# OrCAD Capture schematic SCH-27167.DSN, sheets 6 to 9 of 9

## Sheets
6 Elevator Connectors: size C
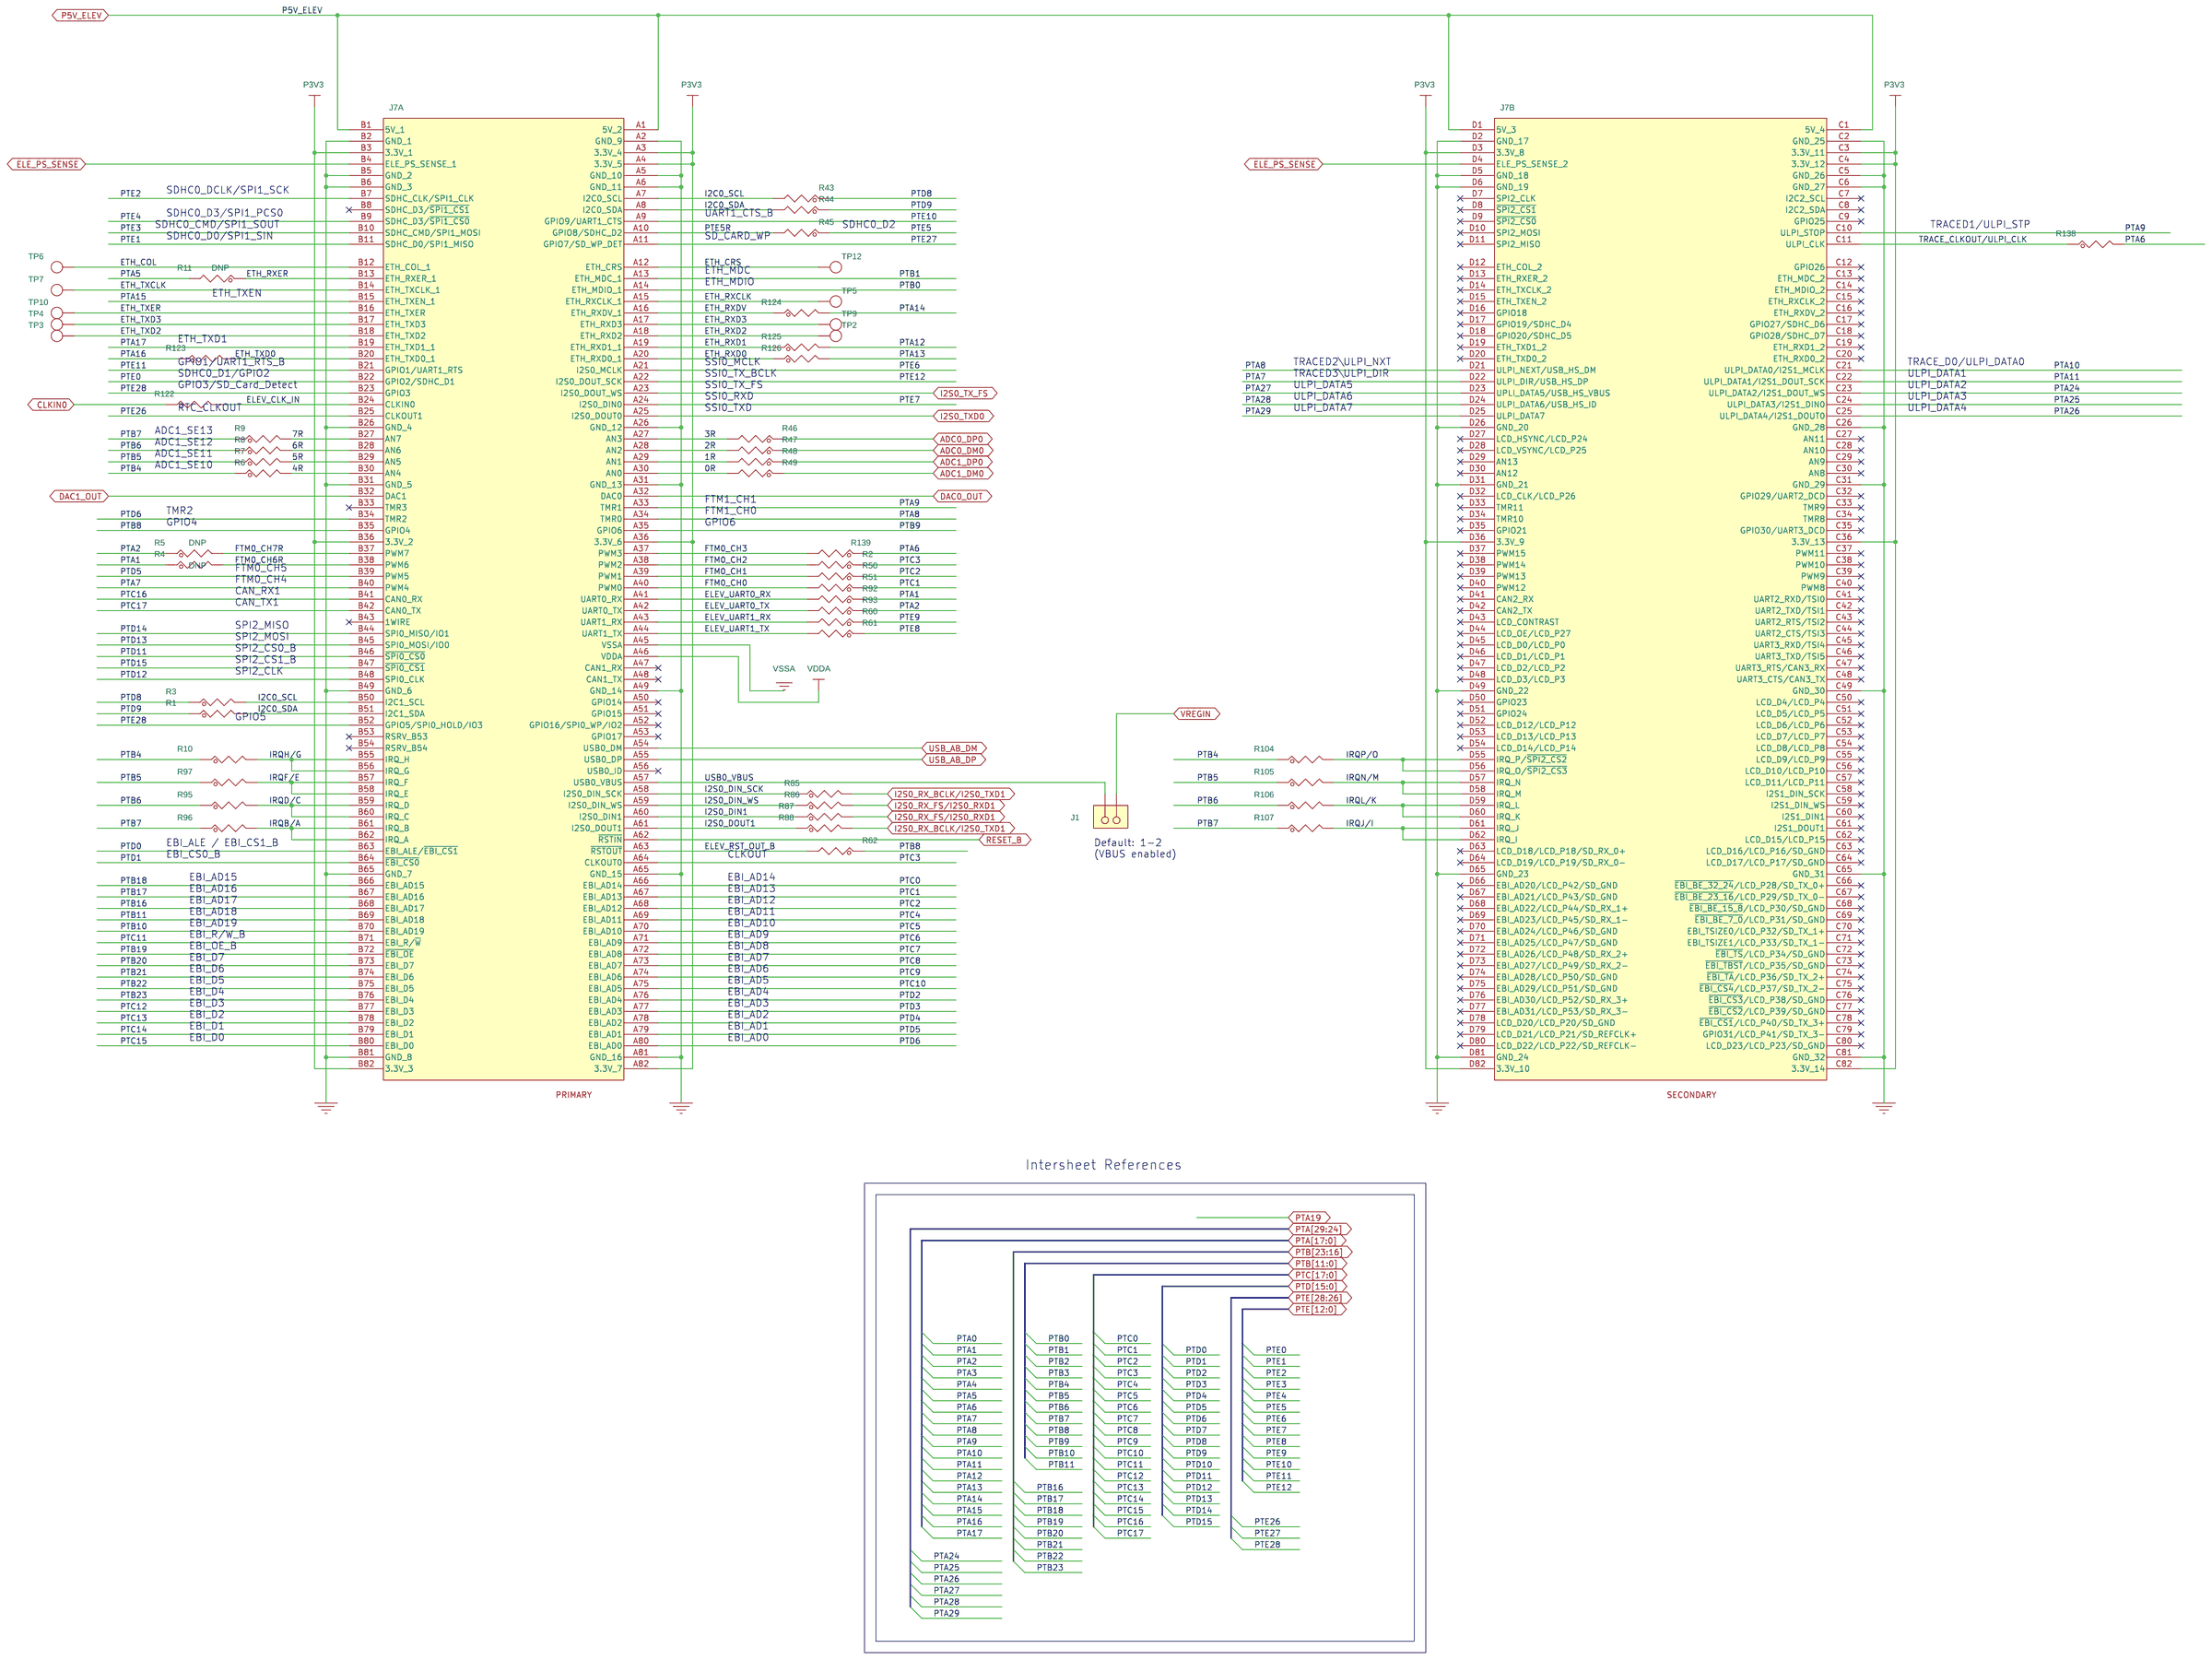
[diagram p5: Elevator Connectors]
7 02 Notes
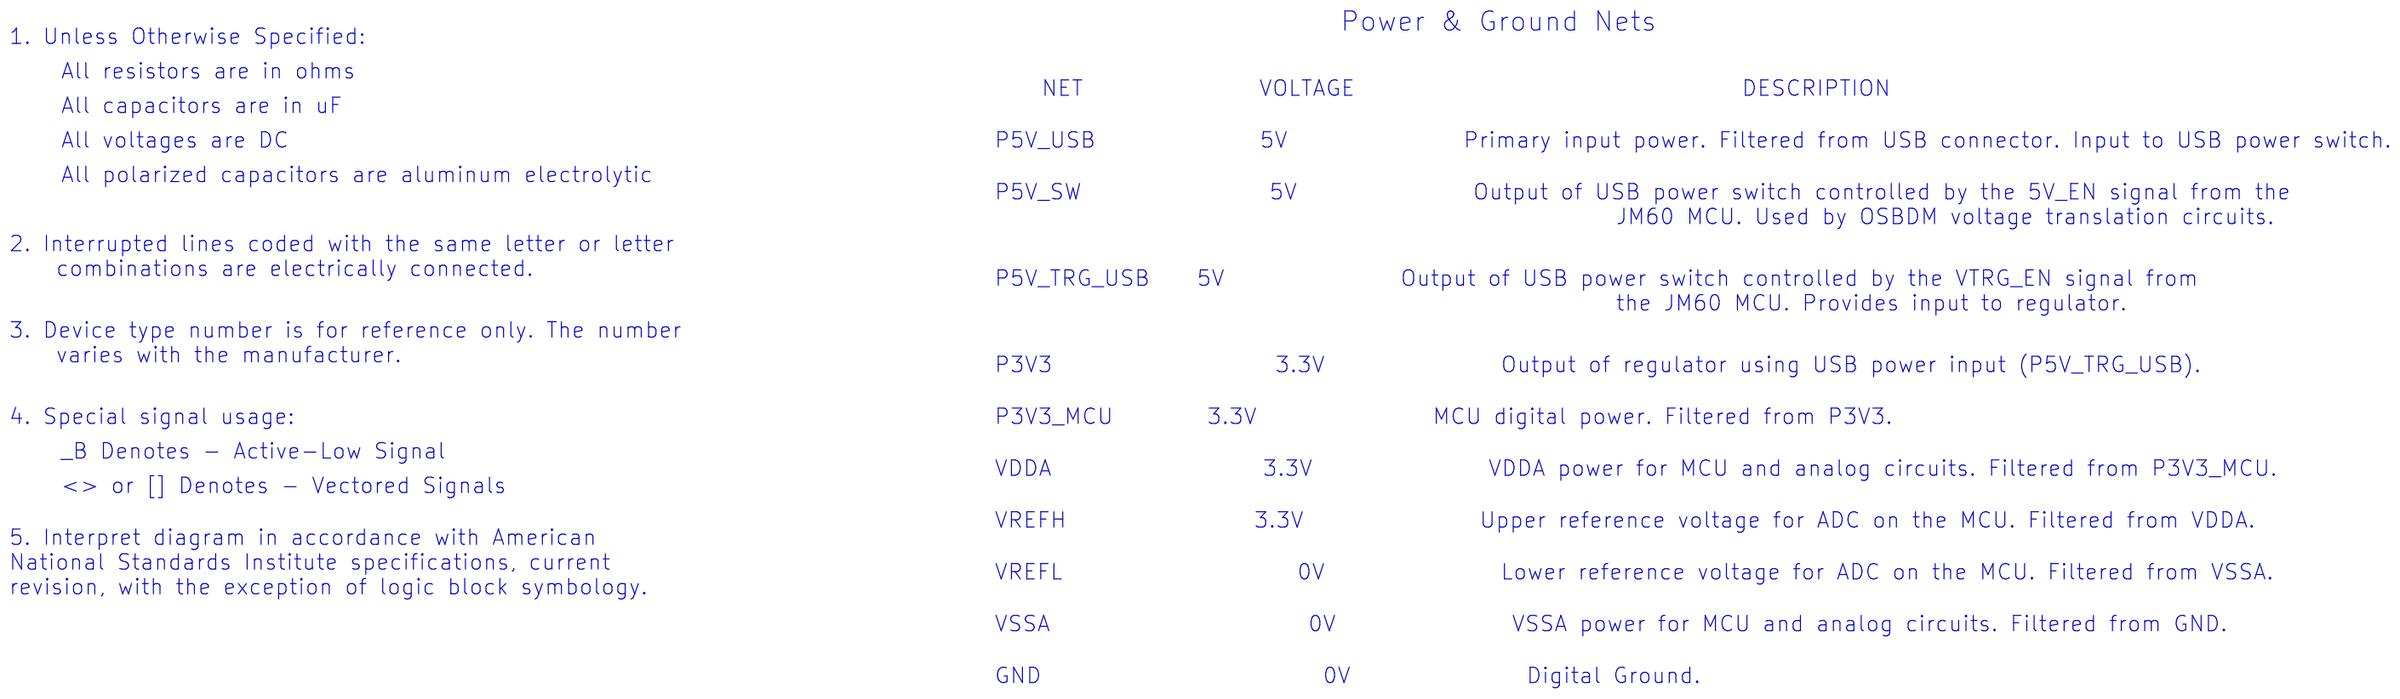
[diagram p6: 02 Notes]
8 03 Block Diagram
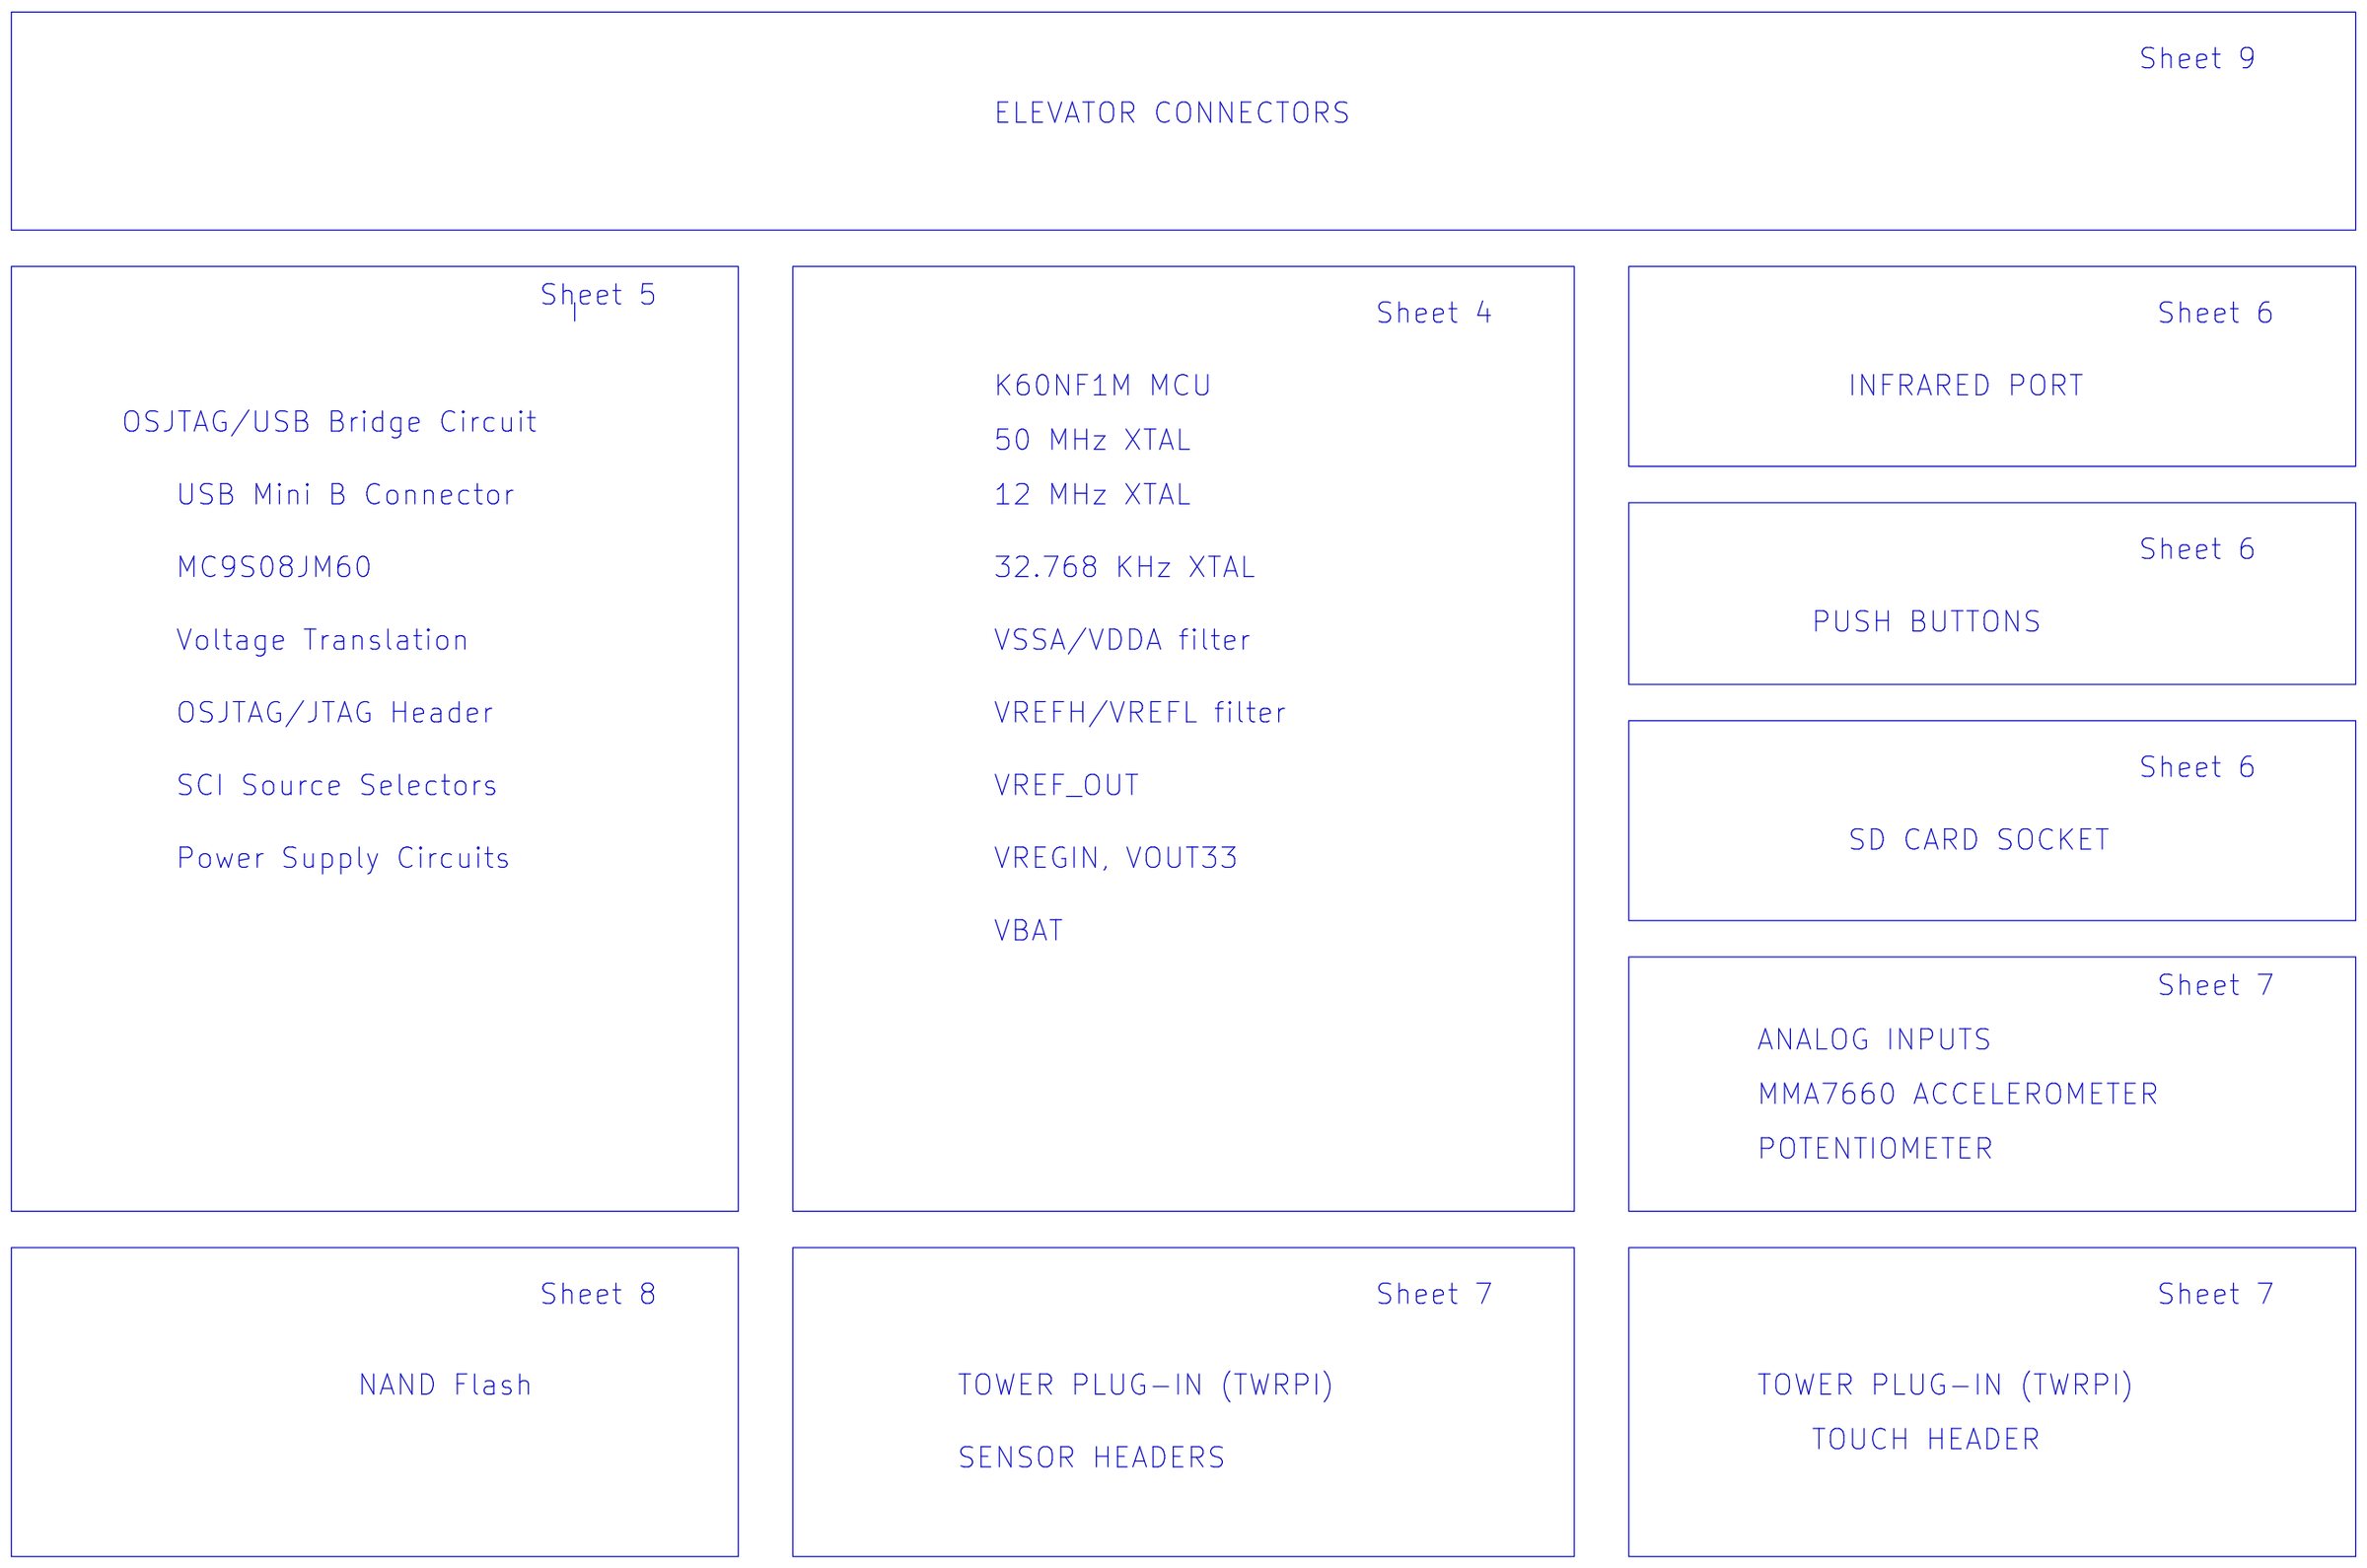
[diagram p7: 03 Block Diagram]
9 01 Table of Contents/Revisions
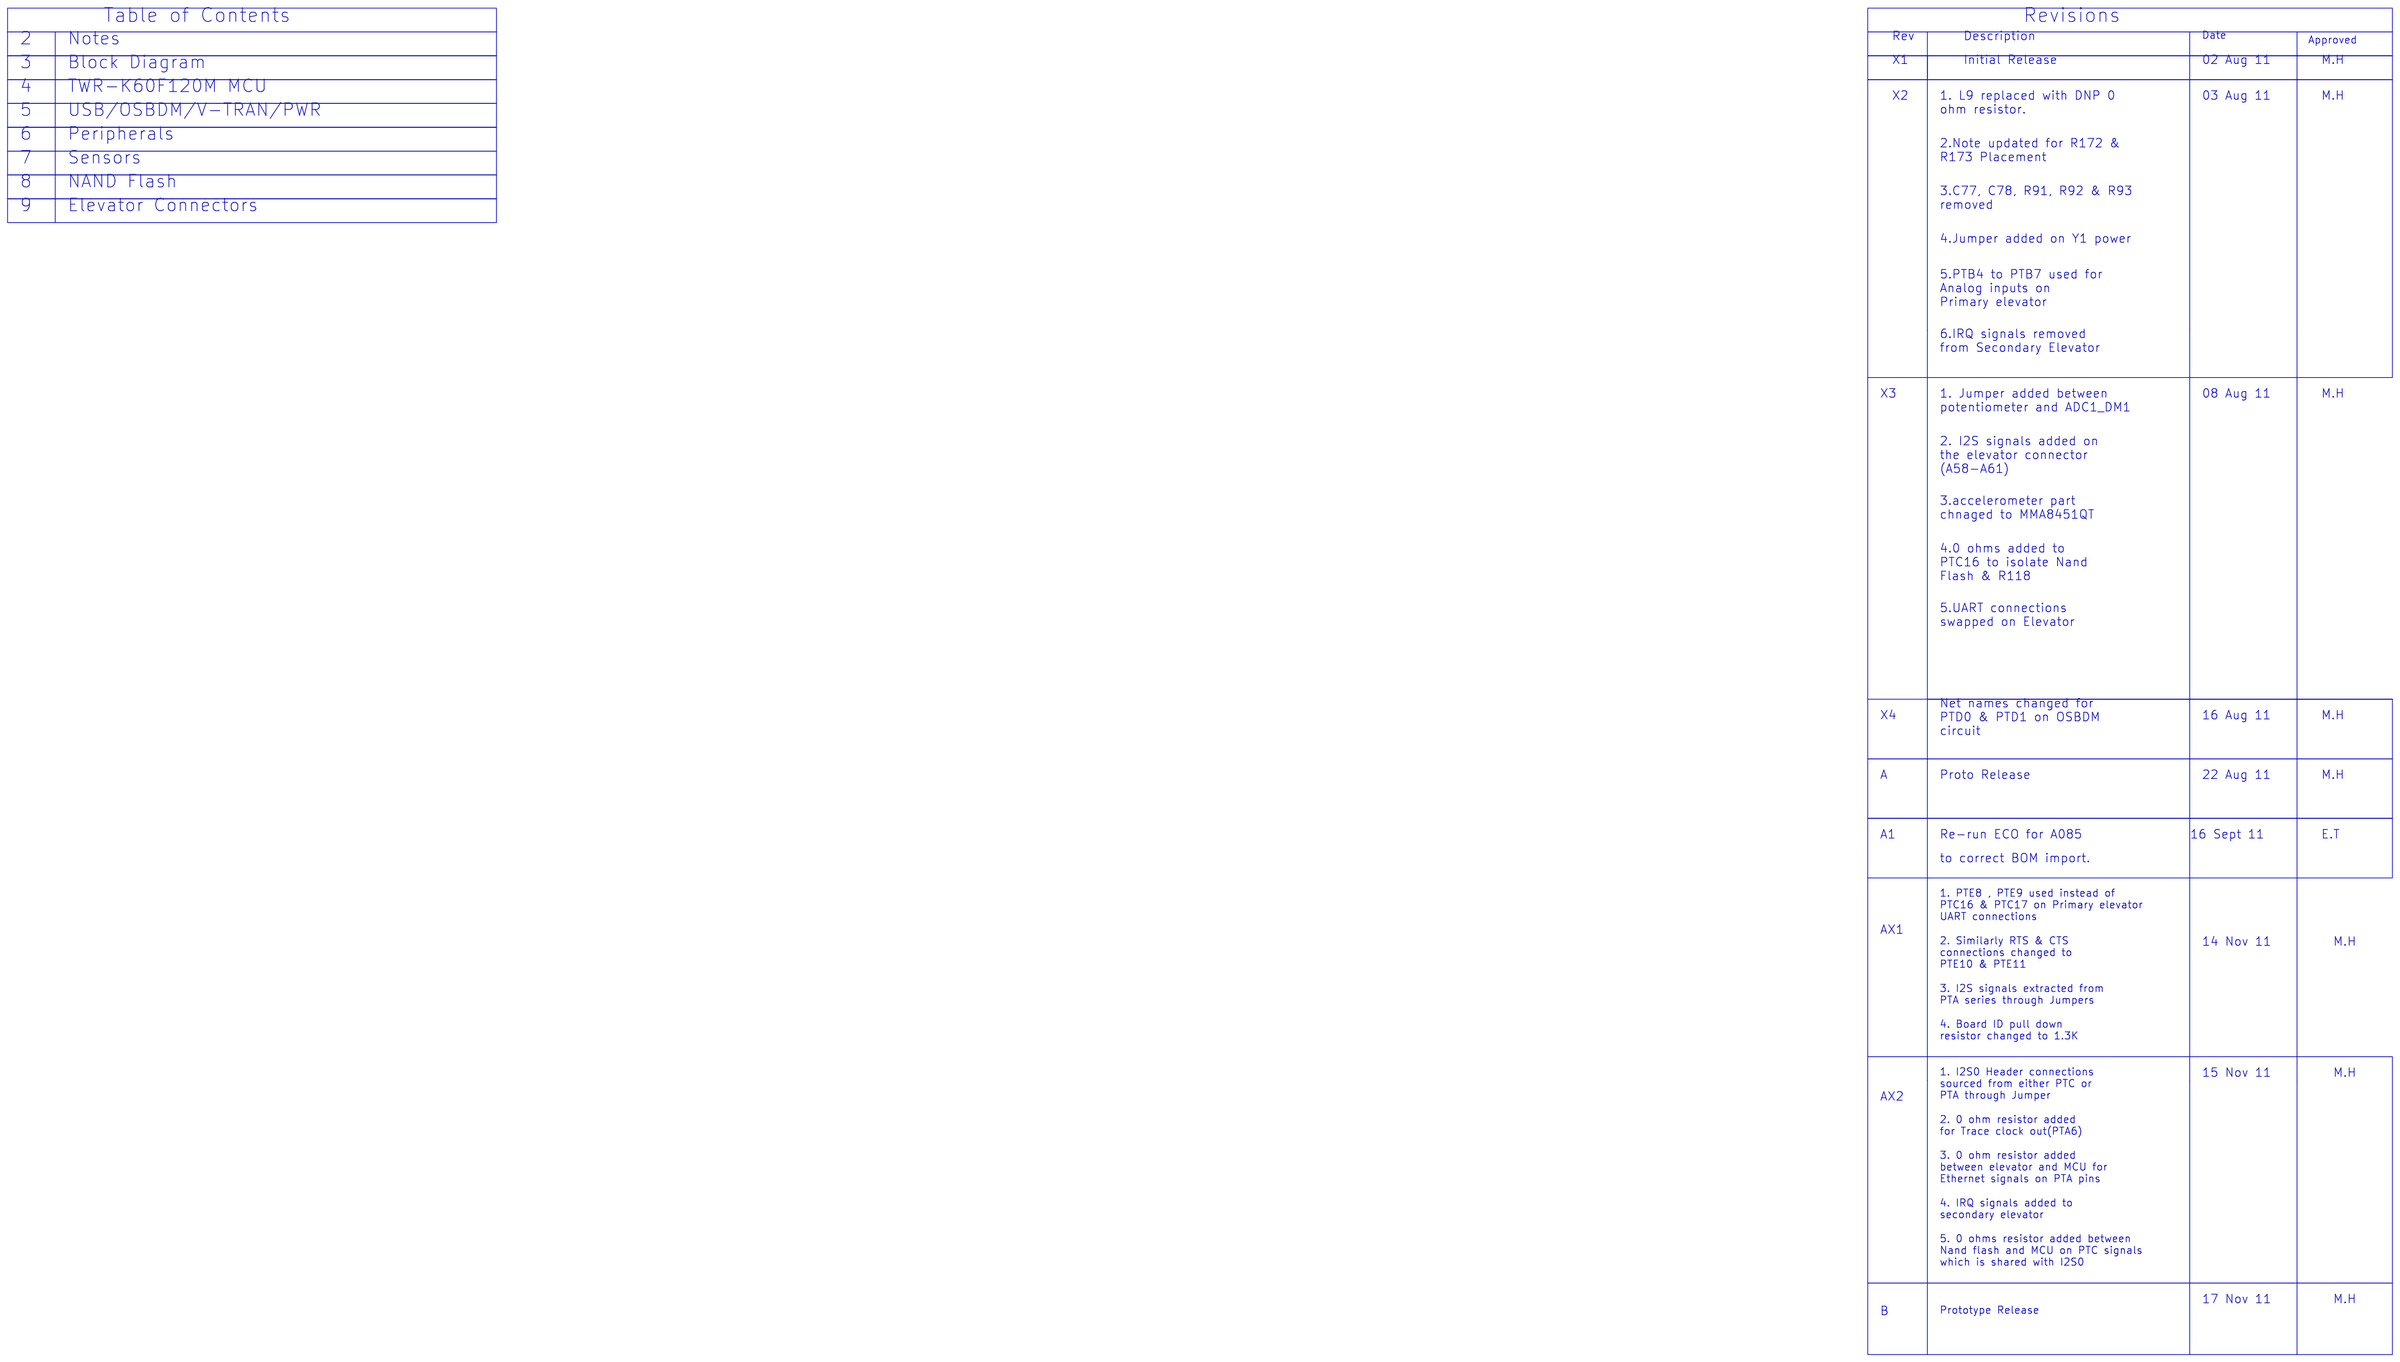
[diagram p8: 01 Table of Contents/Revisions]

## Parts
J1  HDR 1X2 TH  [HDR102]
J7  PCI EXPRESS TOWER SYSTEM  [cn2x82_finger_ass]  (sections A,B)
R1  0  [RC0603_OV]
R2  0  [RC0603_OV]
R3  0  [RC0603_OV]
R4  0  [RC0603_OV]
R5  0  [RC0603_OV]
R6  0  [RC0603_OV]
R7  0  [RC0603_OV]
R8  0  [RC0603_OV]
R9  0  [RC0603_OV]
R10  0  [RC0603_OV]
R11  0  [RC0603_OV]
R43  0  [RC0603_OV]
R44  0  [RC0603_OV]
R45  0  [RC0603_OV]
R46  0  [RC0603_OV]
R47  0  [RC0603_OV]
R48  0  [RC0603_OV]
R49  0  [RC0603_OV]
R50  0  [RC0603_OV]
R51  0  [RC0603_OV]
R60  0  [RC0603_OV]
R61  0  [RC0603_OV]
R62  0  [RC0603_OV]
R85  0  [RC0603_OV]
R86  0  [RC0603_OV]
R87  0  [RC0603_OV]
R88  0  [RC0603_OV]
R92  0  [RC0603_OV]
R93  0  [RC0603_OV]
R95  0  [RC0603_OV]
R96  0  [RC0603_OV]
R97  0  [RC0603_OV]
R104  0  [RC0603_OV]
R105  0  [RC0603_OV]
R106  0  [RC0603_OV]
R107  0  [RC0603_OV]
R122  0  [RC0603_OV]
R123  0  [RC0603_OV]
R124  0  [RC0603_OV]
R125  0  [RC0603_OV]
R126  0  [RC0603_OV]
R138  0  [RC0805_OV]
R139  0  [RC0805_OV]
TP2  TPAD_040  [TPAD_040]
TP3  TPAD_040  [TPAD_040]
TP4  TPAD_040  [TPAD_040]
TP5  TPAD_040  [TPAD_040]
TP6  TPAD_040  [TPAD_040]
TP7  TPAD_040  [TPAD_040]
TP9  TPAD_040  [TPAD_040]
TP10  TPAD_040  [TPAD_040]
TP12  TPAD_040  [TPAD_040]

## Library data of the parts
J1 = CONN_HDR_2X1: HDR 1X2 TH 100MIL SP 339H AU 98L; AGILE_PN: 210-75439; CAD_APPROVED: YES; HEIGHT: 8.71 MM; MFG_NAME01: SAMTEC; MFG_PN01: TSW-102-07-G-S; ROHS: Yes
J7 = CONN_PCI_XPRESS_X16_328P: CON DUAL 2X82 Edge PCI Express SMT 1MM SP 591H FOR TOWER SYSTEM NOT A PART TO ORDER; AGILE_PN: 211-78844; CAD_APPROVED: Yes; HEIGHT: 15.01MM; MFG_NAME01: NA; MFG_PN01: EDGE PCI EXPRESS 164; ROHS: Yes
R1-R3 R6-R10 R43-R51 R60-R62 R85-R88 R92 R93 R95-R97 R104-R107 R122-R126 = RES: RES MF ZERO OHM 1/10W -- 0603; AGILE_PN: 470-75407; CAD_APPROVED: Yes; FPLIST: RC0603_OV,RC0603,R603-X2,0603_CC; MFG_NAME01: VISHAY INTERTECHNOLOGY; MFG_PN01: CRCW06030000Z0EA; ROHS: Yes; Tolerance: 1%
R4 R5 R11 = RES: RES MF ZERO OHM 1/10W -- 0603; AGILE_PN: 470-75407; ASSY_OPT: DNP; CAD_APPROVED: Yes; FPLIST: RC0603_OV,RC0603,R603-X2,0603_CC; MFG_NAME01: VISHAY INTERTECHNOLOGY; MFG_PN01: CRCW06030000Z0EA; ROHS: Yes; Tolerance: 1%
R138 R139 = RES: RES MF ZERO OHM 1/8W -- 0805; AGILE_PN: 470-75442; CAD_APPROVED: Yes; FPLIST: RC0805_OV,RC0805,0805_CC; MFG_NAME01: YAGEO AMERICA; MFG_PN01: RC0805JR-070RL; ROHS: Yes; Tolerance: 5%
TP2-TP7 TP9 TP10 TP12 = TestLoop: TEST POINT PAD 40MIL DIA SMT, NO PART TO ORDER; AGILE_PN: 211-76643; CAD_APPROVED: Yes; HEIGHT: 0.1MM; MFG_NAME01: NOTACOMPONENT; MFG_PN01: NOTACOMPONENT; ROHS: Yes

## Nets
GND: J7.A2(GND_9) J7.A5(GND_10) J7.A6(GND_11) J7.A26(GND_12) J7.A31(GND_13) J7.A49(GND_14) J7.A65(GND_15) J7.A81(GND_16) J7.B2(GND_1) J7.B5(GND_2) J7.B6(GND_3) J7.B26(GND_4) J7.B31(GND_5) J7.B49(GND_6) J7.B65(GND_7) J7.B81(GND_8) J7.C2(GND_25) J7.C5(GND_26) J7.C6(GND_27) J7.C26(GND_28) J7.C31(GND_29) J7.C49(GND_30) J7.C65(GND_31) J7.C81(GND_32) J7.D2(GND_17) J7.D5(GND_18) J7.D6(GND_19) J7.D26(GND_20) J7.D31(GND_21) J7.D49(GND_22) J7.D65(GND_23) J7.D81(GND_24) ; also on sheet 1 2 3 4 5
P3V3: J7.A3(3.3V_4) J7.A4(3.3V_5) J7.A36(3.3V_6) J7.A82(3.3V_7) J7.B3(3.3V_1) J7.B36(3.3V_2) J7.B82(3.3V_3) J7.C3(3.3V_11) J7.C4(3.3V_12) J7.C36(3.3V_13) J7.C82(3.3V_14) J7.D3(3.3V_8) J7.D36(3.3V_9) J7.D82(3.3V_10) ; also on sheet 1 2 3 4 5
P5V_ELEV: J7.A1(5V_2) J7.B1(5V_1) J7.C1(5V_4) J7.D1(5V_3) ; also on sheet 2
VDDA: J7.A46(VDDA) ; also on sheet 1 4
VSSA: J7.A45(VSSA) ; also on sheet 1 4
0R: J7.A30(AN0) R49.2
1R: J7.A29(AN1) R48.2
2R: J7.A28(AN2) R47.2
3R: J7.A27(AN3) R46.2
4R: J7.B30(AN4) R6.2
5R: J7.B29(AN5) R7.2
6R: J7.B28(AN6) R8.2
7R: J7.B27(AN7) R9.2
ADC0_DM0: R47.1 ; also on sheet 1 4
ADC0_DP0: R46.1 ; also on sheet 1 4
ADC1_DM0: R49.1 ; also on sheet 1
ADC1_DP0: R48.1 ; also on sheet 1 4
CLKIN0: R122.1 ; also on sheet 1
DAC0_OUT: J7.A32(DAC0) ; also on sheet 1
DAC1_OUT: J7.B32(DAC1) ; also on sheet 1
ELE_PS_SENSE: J7.B4(ELE_PS_SENSE_1) J7.D4(ELE_PS_SENSE_2) ; also on sheet 2
ELEV_CLK_IN: J7.B24(CLKIN0) R122.2
ELEV_RST_OUT_B: J7.A63(~{RSTOUT}) R62.2
ELEV_UART0_RX: J7.A41(UART0_RX) R92.2
ELEV_UART0_TX: J7.A42(UART0_TX) R93.2
ELEV_UART1_RX: J7.A43(UART1_RX) R60.2
ELEV_UART1_TX: J7.A44(UART1_TX) R61.2
ETH_COL: J7.B12(ETH_COL_1) TP6.1(Pin1)
ETH_CRS: J7.A12(ETH_CRS) TP12.1(Pin1)
ETH_RXCLK: J7.A15(ETH_RXCLK_1) TP5.1(Pin1)
ETH_RXD0: J7.A20(ETH_RXD0_1) R126.1
ETH_RXD1: J7.A19(ETH_RXD1_1) R125.1
ETH_RXD2: J7.A18(ETH_RXD2) TP2.1(Pin1)
ETH_RXD3: J7.A17(ETH_RXD3) TP9.1(Pin1)
ETH_RXDV: J7.A16(ETH_RXDV_1) R124.1
ETH_RXER: J7.B13(ETH_RXER_1) R11.1
ETH_TXCLK: J7.B14(ETH_TXCLK_1) TP7.1(Pin1)
ETH_TXD0: J7.B20(ETH_TXD0_1) R123.2
ETH_TXD2: J7.B18(ETH_TXD2) TP3.1(Pin1)
ETH_TXD3: J7.B17(ETH_TXD3) TP4.1(Pin1)
ETH_TXER: J7.B16(ETH_TXER) TP10.1(Pin1)
FTM0_CH0: J7.A40(PWM0) R51.2
FTM0_CH1: J7.A39(PWM1) R50.2
FTM0_CH2: J7.A38(PWM2) R2.2
FTM0_CH3: J7.A37(PWM3) R139.2
FTM0_CH6R: J7.B38(PWM6) R4.2
FTM0_CH7R: J7.B37(PWM7) R5.2
I2C0_SCL: J7.A7(I2C0_SCL) J7.B50(I2C1_SCL) R3.2 R43.2
I2C0_SDA: J7.A8(I2C0_SDA) J7.B51(I2C1_SDA) R1.2 R44.2
I2S0_DIN1: J7.A60(I2S0_DIN1) R87.1
I2S0_DIN_SCK: J7.A58(I2S0_DIN_SCK) R85.1
I2S0_DIN_WS: J7.A59(I2S0_DIN_WS) R86.1
I2S0_DOUT1: J7.A61(I2S0_DOUT1) R88.1
I2S0_RX_BCLK/I2S0_TXD1: R85.2 R88.2 ; also on sheet 3
I2S0_RX_FS/I2S0_RXD1: R86.2 R87.2 ; also on sheet 3
I2S0_TX_FS: J7.A23(I2S0_DOUT_WS) ; also on sheet 3
I2S0_TXD0: J7.A25(I2S0_DOUT0) ; also on sheet 3
IRQB/A: J7.B61(IRQ_B) J7.B62(IRQ_A) R96.2
IRQD/C: J7.B59(IRQ_D) J7.B60(IRQ_C) R95.2
IRQF/E: J7.B57(IRQ_F) J7.B58(IRQ_E) R97.2
IRQH/G: J7.B55(IRQ_H) J7.B56(IRQ_G) R10.2
IRQJ/I: J7.D61(IRQ_J) J7.D62(IRQ_I) R107.2
IRQL/K: J7.D59(IRQ_L) J7.D60(IRQ_K) R106.2
IRQN/M: J7.D57(IRQ_N) J7.D58(IRQ_M) R105.2
IRQP/O: J7.D55(IRQ_P/~{SPI2_CS2}) J7.D56(IRQ_O/~{SPI2_CS3}) R104.2
PTA1: R4.1 R92.1 ; also on sheet 1 2
PTA2: R5.1 R93.1 ; also on sheet 1 2
PTA5: R11.2 ; also on sheet 1
PTA6: R138.2 R139.1 ; also on sheet 1 2
PTA7: J7.B40(PWM4) J7.D22(ULPI_DIR/USB_HS_DP) ; also on sheet 1 2
PTA8: J7.A34(TMR0) J7.D21(ULPI_NEXT/USB_HS_DM) ; also on sheet 1 2
PTA9: J7.A33(TMR1) J7.C10(ULPI_STOP) ; also on sheet 1 2
PTA10: J7.C21(ULPI_DATA0/I2S1_MCLK) ; also on sheet 1 2 4
PTA11: J7.C22(ULPI_DATA1/I2S1_DOUT_SCK) ; also on sheet 1 4
PTA12: R125.2 ; also on sheet 1 3
PTA13: R126.2 ; also on sheet 1 3
PTA14: R124.2 ; also on sheet 1 3
PTA15: J7.B15(ETH_TXEN_1) ; also on sheet 1
PTA16: R123.1 ; also on sheet 1 3
PTA17: J7.B19(ETH_TXD1_1) ; also on sheet 1
PTA24: J7.C23(ULPI_DATA2/I2S1_DOUT_WS) ; also on sheet 1
PTA25: J7.C24(ULPI_DATA3/I2S1_DIN0) ; also on sheet 1
PTA26: J7.C25(ULPI_DATA4/I2S1_DOUT0) ; also on sheet 1
PTA27: J7.D23(UPLI_DATA5/USB_HS_VBUS) ; also on sheet 1
PTA28: J7.D24(ULPI_DATA6/USB_HS_ID) ; also on sheet 1 4
PTA29: J7.D25(ULPI_DATA7) ; also on sheet 1 4
PTB0: J7.A14(ETH_MDIO_1) ; also on sheet 1 4
PTB1: J7.A13(ETH_MDC_1) ; also on sheet 1 4
PTB4: R6.1 R10.1 R104.1 ; also on sheet 1 4
PTB5: R7.1 R97.1 R105.1 ; also on sheet 1
PTB6: R8.1 R95.1 R106.1 ; also on sheet 1
PTB7: R9.1 R96.1 R107.1 ; also on sheet 1 4
PTB8: J7.B35(GPIO4) R62.1 ; also on sheet 1 4
PTB9: J7.A35(GPIO6) ; also on sheet 1 4
PTB10: J7.B70(EBI_AD19) ; also on sheet 1
PTB11: J7.B69(EBI_AD18) ; also on sheet 1
PTB16: J7.B68(EBI_AD17) ; also on sheet 1 4
PTB17: J7.B67(EBI_AD16) ; also on sheet 1 4
PTB18: J7.B66(EBI_AD15) ; also on sheet 1 4
PTB19: J7.B72(~{EBI_OE}) ; also on sheet 1 4
PTB20: J7.B73(EBI_D7) ; also on sheet 1 5
PTB21: J7.B74(EBI_D6) ; also on sheet 1 5
PTB22: J7.B75(EBI_D5) ; also on sheet 1 5
PTB23: J7.B76(EBI_D4) ; also on sheet 1 5
PTC0: J7.A66(EBI_AD14) ; also on sheet 1 3 4 5
PTC1: J7.A67(EBI_AD13) R51.1 ; also on sheet 1 3 4 5
PTC2: J7.A68(EBI_AD12) R50.1 ; also on sheet 1 3 4 5
PTC3: J7.A64(CLKOUT0) R2.1 ; also on sheet 1
PTC4: J7.A69(EBI_AD11) ; also on sheet 1 5
PTC5: J7.A70(EBI_AD10) ; also on sheet 1 5
PTC6: J7.A71(EBI_AD9) ; also on sheet 1 3 5
PTC7: J7.A72(EBI_AD8) ; also on sheet 1 5
PTC8: J7.A73(EBI_AD7) ; also on sheet 1 5
PTC9: J7.A74(EBI_AD6) ; also on sheet 1 5
PTC10: J7.A75(EBI_AD5) ; also on sheet 1 5
PTC11: J7.B71(EBI_R/~{W}) ; also on sheet 1 3 5
PTC12: J7.B77(EBI_D3) ; also on sheet 1
PTC13: J7.B78(EBI_D2) ; also on sheet 1
PTC14: J7.B79(EBI_D1) ; also on sheet 1
PTC15: J7.B80(EBI_D0) ; also on sheet 1
PTC16: J7.B41(CAN0_RX) ; also on sheet 1 5
PTC17: J7.B42(CAN0_TX) ; also on sheet 1 5
PTD0: J7.B63(EBI_ALE/~{EBI_CS1}) ; also on sheet 1
PTD1: J7.B64(~{EBI_CS0}) ; also on sheet 1
PTD2: J7.A76(EBI_AD4) ; also on sheet 1
PTD3: J7.A77(EBI_AD3) ; also on sheet 1
PTD4: J7.A78(EBI_AD2) ; also on sheet 1 5
PTD5: J7.A79(EBI_AD1) J7.B39(PWM5) ; also on sheet 1 5
PTD6: J7.A80(EBI_AD0) J7.B34(TMR2) ; also on sheet 1
PTD8: R3.1 R43.1 ; also on sheet 1 4 5
PTD9: R1.1 R44.1 ; also on sheet 1 4 5
PTD11: J7.B46(~{SPI0_CS0}) ; also on sheet 1
PTD12: J7.B48(SPI0_CLK) ; also on sheet 1 4
PTD13: J7.B45(SPI0_MOSI/IO0) ; also on sheet 1 4
PTD14: J7.B44(SPI0_MISO/IO1) ; also on sheet 1 4
PTD15: J7.B47(~{SPI0_CS1}) ; also on sheet 1 4
PTE0: J7.B22(GPIO2/SDHC_D1) ; also on sheet 1 3
PTE1: J7.B11(SDHC_D0/SPI1_MISO) ; also on sheet 1 3
PTE2: J7.B7(SDHC_CLK/SPI1_CLK) ; also on sheet 1 3
PTE3: J7.B10(SDHC_CMD/SPI1_MOSI) ; also on sheet 1 3
PTE4: J7.B9(SDHC_D3/~{SPI1_CS0}) ; also on sheet 1 3
PTE5: R45.1 ; also on sheet 1 3
PTE5R: J7.A10(GPIO8/SDHC_D2) R45.2
PTE6: J7.A21(I2S0_MCLK) ; also on sheet 1
PTE7: J7.A24(I2S0_DIN0) ; also on sheet 1
PTE8: R61.1 ; also on sheet 1 2
PTE9: R60.1 ; also on sheet 1 2
PTE10: J7.A9(GPIO9/UART1_CTS) ; also on sheet 1
PTE11: J7.B21(GPIO1/UART1_RTS) ; also on sheet 1
PTE12: J7.A22(I2S0_DOUT_SCK) ; also on sheet 1
PTE26: J7.B25(CLKOUT1) ; also on sheet 1 3 4
PTE27: J7.A11(GPIO7/SD_WP_DET) ; also on sheet 1
PTE28: J7.B23(GPIO3) J7.B52(GPIO5/SPI0_HOLD/IO3) ; also on sheet 1 3
RESET_B: J7.A62(~{RSTIN}) ; also on sheet 1 2 4
TRACE_CLKOUT/ULPI_CLK: J7.C11(ULPI_CLK) R138.1
USB0_VBUS: J1.2 J7.A57(USB0_VBUS)
USB_AB_DM: J7.A54(USB0_DM) ; also on sheet 1
USB_AB_DP: J7.A55(USB0_DP) ; also on sheet 1
VREGIN: J1.1 ; also on sheet 1

Not connected (* = marked no-connect by the designer): J7 A47(CAN1_RX)* A48(CAN1_TX)* A50(GPIO14)* A51(GPIO15)* A52(GPIO16/SPI0_WP/IO2)* A53(GPIO17)* A56(USB0_ID)* B8(SDHC_D3/~{SPI1_CS1})* B33(TMR3)* B43(1WIRE)* B53(RSRV)* B54(RSRV)* C7(I2C2_SCL)* C8(I2C2_SDA)* C9(GPIO25)* C12(GPIO26)* C13(ETH_MDC_2)* C14(ETH_MDIO_2)* C15(ETH_RXCLK_2)* C16(ETH_RXDV_2)* C17(GPIO27/SDHC_D6)* C18(GPIO28/SDHC_D7)* C19(ETH_RXD1_2)* C20(ETH_RXD0_2)* C27(AN11)* C28(AN10)* C29(AN9)* C30(AN8)* C32(GPIO29/UART2_DCD)* C33(TMR9)* C34(TMR8)* C35(GPIO30/UART3_DCD)* C37(PWM11)* C38(PWM10)* C39(PWM9)* C40(PWM8)* C41(UART2_RXD/TSI0)* C42(UART2_TXD/TSI1)* C43(UART2_RTS/TSI2)* C44(UART2_CTS/TSI3)* C45(UART3_RXD/TSI4)* C46(UART3_TXD/TSI5)* C47(UART3_RTS/CAN3_RX)* C48(UART3_CTS/CAN3_TX)* C50(LCD_D4/LCD_P4)* C51(LCD_D5/LCD_P5)* C52(LCD_D6/LCD_P6)* C53(LCD_D7/LCD_P7)* C54(LCD_D8/LCD_P8)* C55(LCD_D9/LCD_P9)* C56(LCD_D10/LCD_P10)* C57(LCD_D11/LCD_P11)* C58(I2S1_DIN_SCK)* C59(I2S1_DIN_WS)* C60(I2S1_DIN1)* C61(I2S1_DOUT1)* C62(LCD_D15/LCD_P15)* C63(LCD_D16/LCD_P16/SD_GND)* C64(LCD_D17/LCD_P17/SD_GND)* C66(~{EBI_BE_32_24}/LCD_P28/SD_TX_0+)* C67(~{EBI_BE_23_16}/LCD_P29/SD_TX_0-)* C68(~{EBI_BE_15_8}/LCD_P30/SD_GND)* C69(~{EBI_BE_7_0}/LCD_P31/SD_GND)* C70(EBI_TSIZE0/LCD_P32/SD_TX_1+)* C71(EBI_TSIZE1/LCD_P33/SD_TX_1-)* C72(~{EBI_TS}/LCD_P34/SD_GND)* C73(~{EBI_TBST}/LCD_P35/SD_GND)* C74(~{EBI_TA}/LCD_P36/SD_TX_2+)* C75(~{EBI_CS4}/LCD_P37/SD_TX_2-)* C76(~{EBI_CS3}/LCD_P38/SD_GND)* C77(~{EBI_CS2}/LCD_P39/SD_GND)* C78(~{EBI_CS1}/LCD_P40/SD_TX_3+)* C79(GPIO31/LCD_P41/SD_TX_3-)* C80(LCD_D23/LCD_P23/SD_GND)* D7(SPI2_CLK)* D8(~{SPI2_CS1})* D9(~{SPI2_CS0})* D10(SPI2_MOSI)* D11(SPI2_MISO)* D12(ETH_COL_2)* D13(ETH_RXER_2)* D14(ETH_TXCLK_2)* D15(ETH_TXEN_2)* D16(GPIO18)* D17(GPIO19/SDHC_D4)* D18(GPIO20/SDHC_D5)* D19(ETH_TXD1_2)* D20(ETH_TXD0_2)* D27(LCD_HSYNC/LCD_P24)* D28(LCD_VSYNC/LCD_P25)* D29(AN13)* D30(AN12)* D32(LCD_CLK/LCD_P26)* D33(TMR11)* D34(TMR10)* D35(GPIO21)* D37(PWM15)* D38(PWM14)* D39(PWM13)* D40(PWM12)* D41(CAN2_RX)* D42(CAN2_TX)* D43(LCD_CONTRAST)* D44(LCD_OE/LCD_P27)* D45(LCD_D0/LCD_P0)* D46(LCD_D1/LCD_P1)* D47(LCD_D2/LCD_P2)* D48(LCD_D3/LCD_P3)* D50(GPIO23)* D51(GPIO24)* D52(LCD_D12/LCD_P12)* D53(LCD_D13/LCD_P13)* D54(LCD_D14/LCD_P14)* D63(LCD_D18/LCD_P18/SD_RX_0+)* D64(LCD_D19/LCD_P19/SD_RX_0-)* D66(EBI_AD20/LCD_P42/SD_GND)* D67(EBI_AD21/LCD_P43/SD_GND)* D68(EBI_AD22/LCD_P44/SD_RX_1+)* D69(EBI_AD23/LCD_P45/SD_RX_1-)* D70(EBI_AD24/LCD_P46/SD_GND)* D71(EBI_AD25/LCD_P47/SD_GND)* D72(EBI_AD26/LCD_P48/SD_RX_2+)* D73(EBI_AD27/LCD_P49/SD_RX_2-)* D74(EBI_AD28/LCD_P50/SD_GND)* D75(EBI_AD29/LCD_P51/SD_GND)* D76(EBI_AD30/LCD_P52/SD_RX_3+)* D77(EBI_AD31/LCD_P53/SD_RX_3-)* D78(LCD_D20/LCD_P20/SD_GND)* D79(LCD_D21/LCD_P21/SD_REFCLK+)* D80(LCD_D22/LCD_P22/SD_REFCLK-)*

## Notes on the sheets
sheet 6
- SDHC0_DCLK/SPI1_SCK
- SDHC0_D3/SPI1_PCS0
- UART1_CTS_B
- SDHC0_CMD/SPI1_SOUT
- SDHC0_D2
- TRACED1/ULPI_STP
- SDHC0_D0/SPI1_SIN
- SD_CARD_WP
- ETH_MDC
- ETH_MDIO
- ETH_TXEN
- ETH_TXD1
- GPIO1/UART1_RTS_B
- SSI0_MCLK
- TRACED2\ULPI_NXT
- TRACE_D0/ULPI_DATA0
- SDHC0_D1/GPIO2
- SSI0_TX_BCLK
- TRACED3\ULPI_DIR
- ULPI_DATA1
- GPIO3/SD_Card_Detect
- SSI0_TX_FS
- ULPI_DATA5
- ULPI_DATA2
- SSI0_RXD
- ULPI_DATA6
- ULPI_DATA3
- RTC_CLKOUT
- SSI0_TXD
- ULPI_DATA7
- ULPI_DATA4
- ADC1_SE13
- ADC1_SE12
- ADC1_SE11
- ADC1_SE10
- TMR2
- FTM1_CH0
- FTM1_CH1
- GPIO4
- GPIO6
- FTM0_CH4
- FTM0_CH5
- CAN_RX1
- CAN_TX1
- SPI2_MISO
- SPI2_MOSI
- SPI2_CS0_B
- SPI2_CS1_B
- SPI2_CLK
- GPIO5
- EBI_ALE / EBI_CS1_B
- Default: 1-2
  (VBUS enabled)
- EBI_CS0_B
- CLKOUT
- EBI_AD15
- EBI_AD16
- EBI_AD13
- EBI_AD14
- EBI_AD17
- EBI_AD12
- EBI_AD18
- EBI_AD11
- EBI_AD19
- EBI_AD10
- EBI_R/W_B
- EBI_AD9
- EBI_D7
- EBI_OE_B
- EBI_AD7
- EBI_AD8
- EBI_D6
- EBI_AD6
- EBI_D5
- EBI_AD5
- EBI_D4
- EBI_AD4
- EBI_D3
- EBI_AD3
- EBI_D2
- EBI_AD2
- EBI_D0
- EBI_D1
- EBI_AD0
- EBI_AD1
- Intersheet References
sheet 7
- Power & Ground Nets
- 1. Unless Otherwise Specified:
- All resistors are in ohms
- NET               VOLTAGE                                 DESCRIPTION
- All capacitors are in uF
- All voltages are DC
- P5V_USB              5V               Primary input power. Filtered from USB connector. Input to USB power switch.
- All polarized capacitors are aluminum electrolytic
- P5V_SW                5V               Output of USB power switch controlled by the 5V_EN signal from the
                                                       JM60 MCU. Used by OSBDM voltage translation circuits.
- 2. Interrupted lines coded with the same letter or letter
      combinations are electrically connected.
- P5V_TRG_USB    5V               Output of USB power switch controlled by the VTRG_EN signal from
                                                       the JM60 MCU. Provides input to regulator.
- 3. Device type number is for reference only. The number
      varies with the manufacturer.
- P3V3                   3.3V               Output of regulator using USB power input (P5V_TRG_USB).
- 4. Special signal usage:
- P3V3_MCU        3.3V               MCU digital power. Filtered from P3V3.
- _B Denotes - Active-Low Signal
- VDDA                  3.3V               VDDA power for MCU and analog circuits. Filtered from P3V3_MCU.
- <> or [] Denotes - Vectored Signals
- 5. Interpret diagram in accordance with American
  National Standards Institute specifications, current
  revision, with the exception of logic block symbology.
- VREFH                3.3V               Upper reference voltage for ADC on the MCU. Filtered from VDDA.
- VREFL                    0V               Lower reference voltage for ADC on the MCU. Filtered from VSSA.
- VSSA                      0V               VSSA power for MCU and analog circuits. Filtered from GND.
- GND                        0V               Digital Ground.
sheet 8
- Sheet 9
- ELEVATOR CONNECTORS
- Sheet 5
- Sheet 4
- Sheet 6
- K60NF1M MCU
- INFRARED PORT
- OSJTAG/USB Bridge Circuit
- 50 MHz XTAL
- USB Mini B Connector
- 12 MHz XTAL
- Sheet 6
- MC9S08JM60
- 32.768 KHz XTAL
- PUSH BUTTONS
- Voltage Translation
- VSSA/VDDA filter
- OSJTAG/JTAG Header
- VREFH/VREFL filter
- Sheet 6
- SCI Source Selectors
- VREF_OUT
- SD CARD SOCKET
- Power Supply Circuits
- VREGIN, VOUT33
- VBAT
- Sheet 7
- ANALOG INPUTS
- MMA7660 ACCELEROMETER
- POTENTIOMETER
- Sheet 8
- Sheet 7
- Sheet 7
- NAND Flash
- TOWER PLUG-IN (TWRPI)
- TOWER PLUG-IN (TWRPI)
- TOUCH HEADER
- SENSOR HEADERS
sheet 9
- Table of Contents
- Revisions
- 2
- Notes
- Rev
- Description
- Date
- Approved
- 3
- Block Diagram
- X1
- Initial Release
- 02 Aug 11
- M.H
- 4
- TWR-K60F120M MCU
- X2
- 1. L9 replaced with DNP 0
  ohm resistor.
- 03 Aug 11
- M.H
- 5
- USB/OSBDM/V-TRAN/PWR
- 6
- Peripherals
- 2.Note updated for R172 &
  R173 Placement
- 7
- Sensors
- 8
- NAND Flash
- 3.C77, C78, R91, R92 & R93
  removed
- 9
- Elevator Connectors
- 4.Jumper added on Y1 power
- 5.PTB4 to PTB7 used for
  Analog inputs on
  Primary elevator
- 6.IRQ signals removed
  from Secondary Elevator
- X3
- 1. Jumper added between
  potentiometer and ADC1_DM1
- 08 Aug 11
- M.H
- 2. I2S signals added on
  the elevator connector
  (A58-A61)
- 3.accelerometer part
  chnaged to MMA8451QT
- 4.0 ohms added to
  PTC16 to isolate Nand
  Flash & R118
- 5.UART connections
  swapped on Elevator
- Net names changed for
  PTD0 & PTD1 on OSBDM
  circuit
- X4
- 16 Aug 11
- M.H
- A
- Proto Release
- 22 Aug 11
- M.H
- A1
- Re-run ECO for A085
- 16 Sept 11
- E.T
- to correct BOM import.
- 1. PTE8 , PTE9 used instead of
  PTC16 & PTC17 on Primary elevator
  UART connections
- AX1
- 2. Similarly RTS & CTS
  connections changed to
  PTE10 & PTE11
- 14 Nov 11
- M.H
- 3. I2S signals extracted from
  PTA series through Jumpers
- 4. Board ID pull down
  resistor changed to 1.3K
- 1. I2S0 Header connections
  sourced from either PTC or
  PTA through Jumper
- 15 Nov 11
- M.H
- AX2
- 2. 0 ohm resistor added
  for Trace clock out(PTA6)
- 3. 0 ohm resistor added
  between elevator and MCU for
  Ethernet signals on PTA pins
- 4. IRQ signals added to
  secondary elevator
- 5. 0 ohms resistor added between
  Nand flash and MCU on PTC signals
  which is shared with I2S0
- B
- Prototype Release
- 17 Nov 11
- M.H
